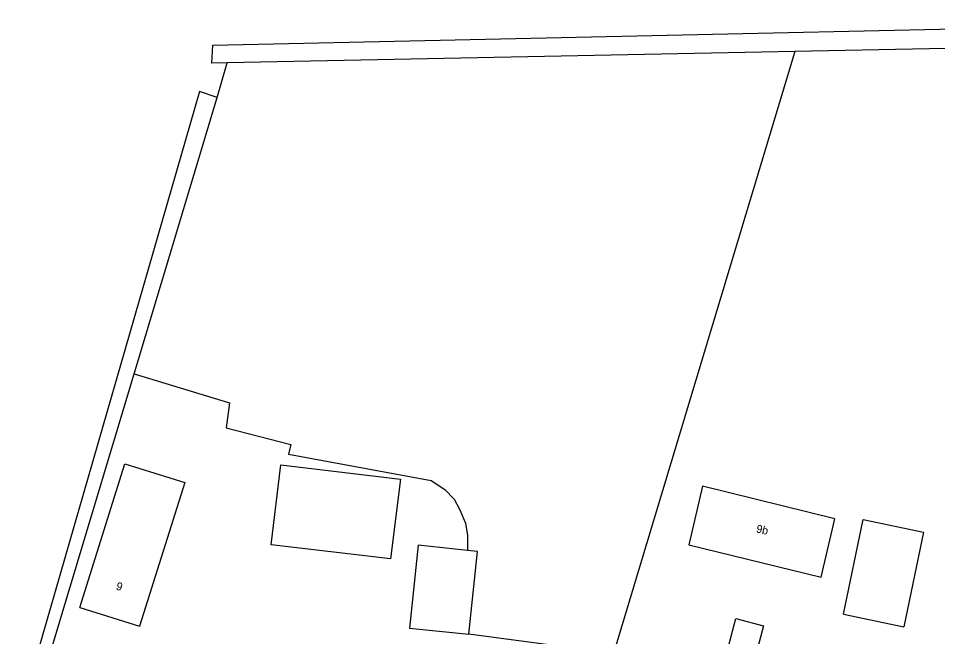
# Model space of a CAD drawing. Extents: x 137000 to 140001, y 403500 to 406000.
# Drawn here: x 138037.1 to 138151.9, y 405558.4 to 405635.7 of the extents above; entities that cross this region are included whole.
import ezdxf

# ---------------------------------------------------------------- set-up
doc = ezdxf.new("R2010")
doc.units = 0
for name, color, linetype in [('gg-anno-huisnummerreeks BGT', 7, 'Continuous'), ('gg-bbg-bijgebouw', 7, 'Continuous'), ('gg-bbg-gedigitaliseerde bebouwing', 7, 'Continuous'), ('gg-bbg-gedigitaliseerde bijgebouw', 7, 'Continuous'), ('gg-bbg-hoofdgebouw', 7, 'Continuous'), ('gg-knt-bronhoudergrens', 7, 'Continuous'), ('gg-kntw-bovenkant insteek waterloop', 7, 'Continuous'), ('gg-kntw-greppel-droge sloot', 7, 'Continuous')]:
    doc.layers.add(name, color=color, linetype=linetype)

msp = doc.modelspace()

# ---------------------------------------------------------------- linework, layer by layer
at = {"layer": 'gg-bbg-bijgebouw'}
for p, q in [((138140.19, 405561.22), (138147.74, 405559.66)), ((138085.97, 405559.5), (138093.4, 405558.73))]:
    msp.add_line(p, q, dxfattribs=at)
msp.add_lwpolyline([(138126.75, 405560.67), (138130.2, 405559.76), (138128.92, 405554.89), (138125.47, 405555.79), (138126.75, 405560.67)], dxfattribs=at)
at = {"layer": 'gg-bbg-gedigitaliseerde bebouwing'}
for points in [[(138044.81, 405562.06), (138050.45, 405580.01), (138057.94, 405577.69), (138052.28, 405559.71)], [(138137.39, 405565.87), (138139.09, 405573.16), (138122.57, 405577.21), (138120.88, 405569.91)]]:
    msp.add_lwpolyline(points, dxfattribs=at)
at = {"layer": 'gg-bbg-gedigitaliseerde bijgebouw'}
for points in [[(138068.7, 405569.9), (138069.9, 405579.88), (138084.86, 405578.08), (138083.59, 405568.15), (138068.7, 405569.9)], [(138140.19, 405561.22), (138142.63, 405573.04), (138150.18, 405571.48), (138147.74, 405559.66)], [(138093.24, 405569.19), (138087.05, 405569.85), (138085.97, 405559.5)], [(138093.4, 405558.73), (138094.46, 405569.06), (138093.24, 405569.19)]]:
    msp.add_lwpolyline(points, dxfattribs=at)
at = {"layer": 'gg-bbg-hoofdgebouw'}
for p, q in [((138120.88, 405569.91), (138137.39, 405565.87)), ((138044.81, 405562.06), (138052.28, 405559.71))]:
    msp.add_line(p, q, dxfattribs=at)
at = {"layer": 'gg-knt-bronhoudergrens'}
msp.add_line((138061.96, 405625.79), (138063.2, 405630.11), dxfattribs=at)
for points in [[(138134.11, 405631.51), (138111.47, 405556.32), (138093.4, 405558.73)], [(138051.59, 405591.27), (138063.51, 405587.63), (138063.07, 405584.5), (138071.17, 405582.41), (138070.87, 405581.23), (138088.67, 405577.94), (138090.4, 405576.82), (138091.55, 405575.58), (138092.26, 405574.27), (138092.97, 405572.6), (138093.24, 405571.06), (138093.24, 405569.19)]]:
    msp.add_lwpolyline(points, dxfattribs=at)
at = {"layer": 'gg-kntw-bovenkant insteek waterloop'}
msp.add_line((138134.11, 405631.51), (138063.2, 405630.11), dxfattribs=at)
for points in [[(138063.2, 405630.11), (138061.31, 405630.07), (138061.43, 405632.32), (138212.76, 405635.67)], [(138242.19, 405554.73), (138213.84, 405633.09), (138134.11, 405631.51)]]:
    msp.add_lwpolyline(points, dxfattribs=at)
at = {"layer": 'gg-kntw-greppel-droge sloot'}
for p, q in [((138051.59, 405591.27), (138061.96, 405625.79)), ((138038.54, 405547.78), (138051.59, 405591.27))]:
    msp.add_line(p, q, dxfattribs=at)
msp.add_lwpolyline([(138061.96, 405625.79), (138059.75, 405626.52), (138037.13, 405548.19)], dxfattribs=at)

# ---------------------------------------------------------------- texts
at = {"layer": 'gg-anno-huisnummerreeks BGT'}
for s, rotation, p in [('9b', 346.2, (138129.21, 405571.48)), ('9', 342.5, (138049.25, 405564.33))]:
    msp.add_text(s, height=1, rotation=rotation, dxfattribs=at).set_placement(p)

doc.saveas('drawing.dxf')
